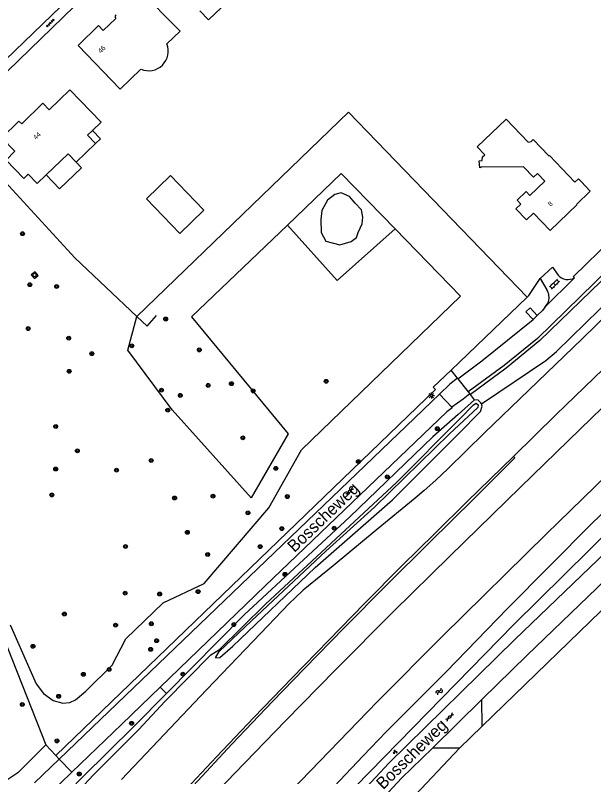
# Model space of a CAD drawing. Extents: x 137999 to 141000, y 397500 to 400501.
# Drawn here: x 138562.8 to 138683.2, y 399077.5 to 399235.9 of the extents above; entities that cross this region are included whole.
import ezdxf

# ---------------------------------------------------------------- set-up
doc = ezdxf.new("R2010")
doc.units = 0
for name, color, linetype in [('gg-afsc-draadraster', 7, 'Continuous'), ('gg-afsc-erfafscheiding', 7, 'Continuous'), ('gg-afsc-hekwerk', 7, 'Continuous'), ('gg-afsc-lijn draadraster', 7, 'Continuous'), ('gg-afsc-muur', 7, 'Continuous'), ('gg-anno-huisnummerreeks BGT', 7, 'Continuous'), ('gg-anno-openbare ruimte label', 7, 'Continuous'), ('gg-bbg-gedigitaliseerde bebouwing', 7, 'Continuous'), ('gg-bbg-gedigitaliseerde bijgebouw', 7, 'Continuous'), ('gg-bbg-hoofdgebouw', 7, 'Continuous'), ('gg-bbg-luifel en loopbrug', 7, 'Continuous'), ('gg-knt-BGT kruinlijn', 7, 'Continuous'), ('gg-knt-bronhoudergrens', 7, 'Continuous'), ('gg-knt-verharding', 7, 'Continuous'), ('gg-kntw-bovenkant insteek waterloop', 7, 'Continuous'), ('gg-kwrk-keermuur', 7, 'Continuous'), ('gt-grn-groengrens', 7, 'Continuous'), ('gt-grn-weggrens', 7, 'Continuous'), ('gt-symb-boom', 7, 'Continuous'), ('gt-symb-gesloten verharding', 7, 'Continuous'), ('gt-symb-groenvak', 7, 'Continuous'), ('gt-symb-klinker verharding', 7, 'Continuous'), ('gt-symb-lichtmast', 7, 'Continuous'), ('gt-symb-rioolschacht', 7, 'Continuous'), ('gt-symb-tegel verharding', 7, 'Continuous'), ('gt-symb-watersymbool', 7, 'Continuous'), ('gx-grn-maaiveld', 7, 'Continuous')]:
    doc.layers.add(name, color=color, linetype=linetype)

# ---------------------------------------------------------------- blocks, each defined once
blk = doc.blocks.new('gt0-KL1')
at = {"layer": 'gt-symb-klinker verharding'}
for p, q in [((-1.15, 0.3), (1.15, 0.3)), ((-1, -0.3), (-1, 0.3)), ((-0.5, 0.3), (-0.5, 0.45)), ((0, -0.3), (0, 0.3)), ((0.5, 0.3), (0.5, 0.45)), ((1, -0.3), (1, 0.3)), ((-1.15, -0.3), (1.15, -0.3)), ((-0.5, -0.45), (-0.5, -0.3)), ((0.5, -0.45), (0.5, -0.3))]:
    blk.add_line(p, q, dxfattribs=at)
blk = doc.blocks.new('gt0-LMAST')
at = {"layer": 'gt-symb-lichtmast'}
for p, q in [((-0.18, 0.17), (-0.45, 0.44)), ((0, 0.25), (0, 0.62)), ((0.17, 0.17), (0.44, 0.44)), ((-0.25, 0), (-0.63, 0)), ((-0.18, -0.18), (-0.45, -0.45)), ((0, -0.25), (0, -0.63)), ((0.44, -0.45), (0.17, -0.18)), ((0.25, 0), (0.62, 0))]:
    blk.add_line(p, q, dxfattribs=at)
blk.add_circle((0, 0), 0.25, dxfattribs=at)
blk = doc.blocks.new('gt0-BOOM')
at = {"layer": 'gt-symb-boom'}
for radius in [0.4, 0.2]:
    blk.add_circle((0, 0), radius, dxfattribs=at)
blk = doc.blocks.new('gt0-GESVH1')
at = {"layer": 'gt-symb-gesloten verharding'}
for p, q in [((-0.99, -0.26), (0.01, 0.24)), ((0.01, -0.26), (-0.99, 0.24)), ((0.01, 0.24), (1.01, -0.26)), ((1.01, 0.24), (0.01, -0.26))]:
    blk.add_line(p, q, dxfattribs=at)
blk = doc.blocks.new('gt0-RS')
at = {"layer": 'gt-symb-rioolschacht'}
blk.add_lwpolyline([(-0.5, -0.5), (0.5, -0.5), (0.5, 0.5), (-0.5, 0.5)], close=True, dxfattribs=at)
blk.add_circle((0, 0), 0.375, dxfattribs=at)
blk = doc.blocks.new('gt0-TEG1')
at = {"layer": 'gt-symb-tegel verharding'}
for p, q in [((-1.13, 0), (1.12, 0)), ((-0.9, -0.25), (-0.9, 0.25)), ((-0.45, -0.25), (-0.45, 0.25)), ((0, -0.25), (0, 0.25)), ((0.45, -0.25), (0.45, 0.25)), ((0.9, -0.25), (0.9, 0.25))]:
    blk.add_line(p, q, dxfattribs=at)
blk = doc.blocks.new('gt0-GRVAK')
at = {"layer": 'gt-symb-groenvak'}
for p, q in [((-0.11, 0.19), (-0.23, 0.24)), ((-0.18, 0.15), (0.09, 0.15)), ((-0.09, 0.21), (-0.16, 0.32)), ((-0.05, 0.21), (-0.05, 0.39)), ((0, 0.21), (0.06, 0.32)), ((0.02, 0.19), (0.13, 0.24)), ((0.26, -0.05), (0.2, 0.06)), ((0.31, -0.05), (0.31, 0.13)), ((0.35, -0.05), (0.41, 0.06)), ((-0.24, -0.23), (-0.36, -0.18)), ((-0.32, -0.26), (-0.05, -0.26)), ((-0.23, -0.21), (-0.29, -0.09)), ((-0.18, -0.2), (-0.18, -0.02)), ((-0.14, -0.21), (-0.07, -0.09)), ((-0.12, -0.23), (0, -0.18)), ((0.24, -0.07), (0.12, -0.02)), ((0.17, -0.11), (0.44, -0.11)), ((0.37, -0.07), (0.49, -0.02))]:
    blk.add_line(p, q, dxfattribs=at)
blk = doc.blocks.new('gt0-WA')
at = {"layer": 'gt-symb-watersymbool'}
for centre, start, end in [((-0.32, 0.02), 28.0725, 151.9275), ((0.43, 0.42), 208.0725, 331.9275), ((-0.32, -0.43), 28.0725, 151.9275), ((0.43, -0.03), 208.0725, 331.9275)]:
    blk.add_arc(centre, 0.425, start, end, dxfattribs=at)

msp = doc.modelspace()

# ---------------------------------------------------------------- linework, layer by layer
at = {"layer": 'gg-afsc-draadraster'}
for p, q in [((138653.48, 399162.09), (138669.32, 399177.31)), ((138649.77, 399158.53), (138653.48, 399162.09))]:
    msp.add_line(p, q, dxfattribs=at)
msp.add_lwpolyline([(138669.32, 399177.31), (138669.64, 399177.61), (138672, 399181.18)], dxfattribs=at)
at = {"layer": 'gg-afsc-erfafscheiding'}
for points in [[(138558.28, 399203.76), (138575.15, 399185.44), (138588.09, 399173.24)], [(138588.09, 399173.24), (138590.2, 399171.25), (138592.17, 399173.46)]]:
    msp.add_lwpolyline(points, dxfattribs=at)
at = {"layer": 'gg-afsc-hekwerk'}
for p, q in [((138542.31, 399151.33), (138569.15, 399084.11)), ((138569.15, 399084.11), (138565.97, 399080.94))]:
    msp.add_line(p, q, dxfattribs=at)
msp.add_lwpolyline([(138565.97, 399080.94), (138563.3, 399078.28), (138558.06, 399074.85), (138539.36, 399056.53), (138534.35, 399053.22), (138530.38, 399049.44)], dxfattribs=at)
at = {"layer": 'gg-afsc-lijn draadraster'}
msp.add_line((138653.48, 399162.09), (138669.32, 399177.31), dxfattribs=at)
msp.add_lwpolyline([(138669.32, 399177.31), (138669.64, 399177.61), (138672, 399181.18)], dxfattribs=at)
at = {"layer": 'gg-afsc-muur'}
for p, q in [((138678.92, 399181.56), (138701.82, 399203.87)), ((138678.9, 399181.54), (138678.92, 399181.56))]:
    msp.add_line(p, q, dxfattribs=at)
at = {"layer": 'gg-bbg-gedigitaliseerde bebouwing'}
for p, q in [((138590.23, 399239.63), (138595.29, 399234.44)), ((138588.94, 399224.73), (138584.59, 399220.53)), ((138574.12, 399220.45), (138580.67, 399213.73)), ((138578.83, 399211.95), (138580.67, 399213.73)), ((138575.43, 399205.37), (138579.49, 399209.27))]:
    msp.add_line(p, q, dxfattribs=at)
for points in [[(138606.6, 399242.05), (138608.37, 399240.22), (138602.96, 399235), (138601.19, 399236.83)], [(138594.32, 399229.97), (138597.06, 399232.61), (138595.29, 399234.44)], [(138579.49, 399209.27), (138577.83, 399210.99), (138578.83, 399211.95)], [(138569.23, 399202.72), (138573.77, 399207.09), (138575.43, 399205.37)], [(138564.55, 399201.96), (138565.47, 399202.85), (138567.35, 399200.91), (138569.23, 399202.72)]]:
    msp.add_lwpolyline(points, dxfattribs=at)
msp.add_arc((138590.55, 399228.46), 4.06, 246.7026, 21.8182, dxfattribs=at)
at = {"layer": 'gg-bbg-gedigitaliseerde bijgebouw'}
msp.add_lwpolyline([(138590.06, 399197.71), (138597.02, 399190.53), (138602.05, 399195.41), (138595.08, 399202.58), (138590.06, 399197.71)], dxfattribs=at)
at = {"layer": 'gg-bbg-hoofdgebouw'}
msp.add_line((138584.59, 399220.53), (138575.83, 399229.62), dxfattribs=at)
for points in [[(138583.7, 399235.29), (138581.05, 399232.77), (138580.09, 399233.78), (138575.83, 399229.62)], [(138574.12, 399220.45), (138569.82, 399216.24), (138568.5, 399217.62), (138564.12, 399213.35), (138563.55, 399213.93), (138559.97, 399210.45), (138562.67, 399207.66)], [(138666.96, 399195.65), (138667.98, 399196.63), (138667.21, 399197.43), (138669.11, 399199.25), (138669.88, 399198.45), (138672.99, 399201.42), (138671.45, 399203.03), (138670.62, 399202.24), (138668.55, 399204.41), (138659.65, 399204.34), (138659.66, 399204.23), (138659.44, 399204.21), (138659.29, 399205.62), (138659.94, 399205.69), (138660.02, 399206.46), (138660.47, 399206.89), (138658.89, 399208.53), (138664.94, 399214.33), (138669.51, 399209.56), (138670.12, 399209.65), (138670.56, 399210.07), (138673.83, 399206.66), (138673.92, 399206.75), (138679.22, 399201.22), (138679.97, 399201.93), (138680.51, 399201.36)], [(138564.55, 399201.96), (138560.86, 399205.8), (138562.67, 399207.66)], [(138666.96, 399195.65), (138669.15, 399193.37), (138670.59, 399194.79), (138674.07, 399191.12), (138679.67, 399196.48), (138679.57, 399196.58), (138682.43, 399199.36), (138680.51, 399201.36)]]:
    msp.add_lwpolyline(points, dxfattribs=at)
msp.add_arc((138584.01, 399235.65), 0.474, 132.2853, 229.3286, dxfattribs=at)
at = {"layer": 'gg-bbg-luifel en loopbrug'}
for points in [[(138579.49, 399209.27), (138580.49, 399210.25), (138578.83, 399211.95)], [(138569.23, 399202.72), (138571.99, 399199.85), (138576.54, 399204.22), (138575.43, 399205.37)]]:
    msp.add_lwpolyline(points, dxfattribs=at)
at = {"layer": 'gg-knt-BGT kruinlijn'}
for p, q in [((138659.03, 399154.3), (138653.13, 399148.84)), ((138655.39, 399152.05), (138658.14, 399154.89)), ((138658.14, 399154.89), (138658.67, 399155.19)), ((138658.67, 399155.19), (138659.12, 399154.9)), ((138659.12, 399154.9), (138659.03, 399154.3)), ((138642.14, 399138.68), (138655.39, 399152.05)), ((138653.13, 399148.84), (138637.55, 399133.57)), ((138614.86, 399113.4), (138642.14, 399138.68)), ((138637.55, 399133.57), (138627.44, 399124.44)), ((138627.44, 399124.44), (138611.96, 399109.92)), ((138605.31, 399103.93), (138614.86, 399113.4)), ((138611.96, 399109.92), (138605.23, 399103.51)), ((138603.46, 399102.83), (138605.31, 399103.93)), ((138604.47, 399102.19), (138605.23, 399103.51)), ((138593.94, 399093.2), (138603.46, 399102.83)), ((138588.4, 399087.23), (138593.94, 399093.2)), ((138579.08, 399077.9), (138588.4, 399087.23)), ((138572.03, 399070.45), (138579.08, 399077.9))]:
    msp.add_line(p, q, dxfattribs=at)
at = {"layer": 'gg-knt-bronhoudergrens'}
for p, q in [((138654.79, 399160.42), (138653.48, 399162.09)), ((138650.24, 399158.03), (138649.77, 399158.53))]:
    msp.add_line(p, q, dxfattribs=at)
at = {"layer": 'gg-knt-verharding'}
for p, q in [((138560.77, 399226.68), (138577.84, 399243.22)), ((138654.79, 399160.42), (138653.24, 399159.19)), ((138653.24, 399159.19), (138651.09, 399157.12)), ((138651.09, 399157.12), (138571.91, 399081.14)), ((138651.09, 399157.12), (138653.61, 399154.38)), ((138653.73, 399154.25), (138652.57, 399153.41)), ((138653.61, 399154.38), (138653.73, 399154.25)), ((138614.79, 399117.23), (138652.57, 399153.41)), ((138592.93, 399096.13), (138614.79, 399117.23)), ((138571.91, 399081.14), (138566.76, 399076.2)), ((138563.14, 399067.46), (138574.54, 399078.41))]:
    msp.add_line(p, q, dxfattribs=at)
for points in [[(138673.34, 399332.19), (138639.6, 399299.52), (138632.54, 399299.67), (138589.36, 399258.02), (138588.89, 399251.3), (138549.57, 399213.15)], [(138571.8, 399000), (138584.07, 399016.51), (138612.13, 399049.83), (138640.56, 399080.38), (138666.74, 399106.01), (138694.44, 399132.57), (138762.01, 399197.52), (138807.68, 399242.38), (138884.6, 399318.08), (138886.05, 399319.54)], [(138672, 399181.18), (138674.55, 399183.49), (138675.73, 399181.86)], [(138657.36, 399157.16), (138655.96, 399156.07), (138653.61, 399154.38)], [(138574.54, 399078.41), (138584.96, 399088.43), (138592.93, 399096.13)]]:
    msp.add_lwpolyline(points, dxfattribs=at)
at = {"layer": 'gg-kntw-bovenkant insteek waterloop'}
msp.add_lwpolyline([(138569.06, 399000), (138599.49, 399037.92), (138630.55, 399072.31), (138666.53, 399109.13), (138692.73, 399135.04), (138766.57, 399206.06), (138805.76, 399244.25), (138841.1, 399278.43), (138881.4, 399317.3), (138882.07, 399318.34)], dxfattribs=at)
at = {"layer": 'gg-kwrk-keermuur'}
msp.add_line((138678.92, 399181.56), (138701.82, 399203.87), dxfattribs=at)
at = {"layer": 'gt-grn-groengrens'}
for p, q in [((138641.82, 399191.5), (138655.44, 399177.49)), ((138571.2, 399081.91), (138650.24, 399158.03)), ((138594.22, 399094.8), (138592.93, 399096.13)), ((138571.2, 399081.91), (138569.15, 399084.11)), ((138571.91, 399081.14), (138571.2, 399081.91))]:
    msp.add_line(p, q, dxfattribs=at)
for points in [[(138669.32, 399177.31), (138632.14, 399215.77), (138588.09, 399173.24)], [(138641.82, 399191.5), (138630.63, 399203.02), (138619.4, 399192.26)], [(138633.77, 399189.67), (138634.15, 399190.71), (138634.95, 399192.54), (138635.14, 399193.96), (138634.8, 399195.45), (138633.5, 399196.83), (138632.35, 399198.21), (138630.59, 399199.01), (138629.29, 399198.63), (138627.76, 399197.44), (138626.54, 399195.3), (138626.38, 399193.46), (138626.42, 399190.74), (138627.38, 399188.95), (138630.32, 399188.18), (138632.69, 399188.87), (138633.77, 399189.67)], [(138619.4, 399192.26), (138599.47, 399173.16), (138619.56, 399148.86), (138611.85, 399135.55), (138595.46, 399153.8), (138586.22, 399166.27), (138588.09, 399173.24)], [(138641.82, 399191.5), (138629.78, 399180.77), (138619.4, 399192.26)], [(138561.7, 399109.1), (138565.8, 399099.77), (138567.14, 399096.82), (138568.62, 399094.81), (138570.63, 399093.33), (138572.64, 399092.8), (138574.11, 399092.93), (138575.32, 399093.47), (138577.46, 399095.3), (138582.95, 399100.66), (138585.77, 399106.16), (138593.54, 399113.67), (138602.12, 399117.69), (138615.51, 399133.45), (138622.34, 399145.51), (138655.44, 399177.49)]]:
    msp.add_lwpolyline(points, dxfattribs=at)
at = {"layer": 'gt-grn-weggrens'}
msp.add_line((138571.91, 399081.14), (138574.54, 399078.41), dxfattribs=at)
at = {"layer": 'gx-grn-maaiveld'}
for p, q in [((138672, 399181.18), (138673.43, 399178.77)), ((138679.16, 399181.31), (138678.92, 399181.56)), ((138679.16, 399181.31), (138679.15, 399181.31)), ((138671.42, 399173.46), (138670.54, 399172.64)), ((138654.88, 399160.31), (138654.79, 399160.42)), ((138654.88, 399160.31), (138657.05, 399157.55)), ((138735.88, 399161.6), (138659.92, 399088)), ((138657.05, 399157.55), (138657.36, 399157.16)), ((138657.36, 399157.16), (138657.49, 399157)), ((138658.37, 399155.88), (138657.49, 399157)), ((138659.87, 399093.52), (138649.62, 399083.44)), ((138659.92, 399088), (138659.87, 399093.52)), ((138659.92, 399088), (138655.21, 399083.4)), ((138655.21, 399083.4), (138618.61, 399044.8)), ((138655.21, 399083.4), (138649.62, 399083.44))]:
    msp.add_line(p, q, dxfattribs=at)
for points in [[(138763.86, 399258.76), (138757.1, 399252.18), (138744.99, 399240.36), (138733.25, 399228.91), (138722.42, 399218.36), (138709.95, 399206.19), (138698.33, 399194.85), (138686.32, 399183.14), (138671.49, 399168.71), (138664.52, 399163.06), (138657.05, 399157.55)], [(138764.45, 399258.41), (138757.56, 399251.7), (138745.46, 399239.9), (138733.73, 399228.4), (138710.44, 399205.69), (138698.76, 399194.36), (138686.8, 399182.65), (138671.97, 399168.24), (138664.93, 399162.51), (138657.49, 399157)], [(138659.77, 399155.09), (138673.16, 399164.09), (138675.41, 399166), (138690.35, 399180.57), (138702.07, 399192.01), (138726.21, 399215.44), (138747.84, 399236.61), (138761.84, 399250.12), (138768.31, 399256.42)], [(138666.44, 399144.15), (138675.36, 399152.88), (138685.11, 399162.29), (138697.02, 399173.84), (138704.59, 399181.28), (138714.01, 399190.41), (138726.38, 399202.33), (138736.1, 399211.81), (138747.46, 399222.75), (138760.29, 399235.26), (138775.8, 399250.27), (138777.29, 399251.74)], [(138782.72, 399248.98), (138780.45, 399246.78), (138754.03, 399221.18), (138729.59, 399197.44), (138715.3, 399183.49), (138703.21, 399172.02), (138691.93, 399161.06), (138680.32, 399149.78), (138667.89, 399137.77), (138653.22, 399123.39), (138641.49, 399111.83), (138629.42, 399099.73), (138619, 399089.09), (138608.45, 399078.21), (138595.11, 399064.19), (138584.24, 399052.51), (138573.94, 399041.33), (138564.83, 399031.26), (138555.63, 399021.02), (138546.98, 399011.39), (138536.29, 398999.15), (138526.38, 398987.5), (138517.55, 398976.85), (138515.33, 398974.12)], [(138563.93, 398999.16), (138566.36, 399001.99), (138568.83, 399004.91), (138590.2, 399031.73), (138597.25, 399040.05), (138601.66, 399045.12), (138612.41, 399057.05), (138626.74, 399072.88), (138635.18, 399081.84), (138639.93, 399086.79), (138652.44, 399099.34), (138665.21, 399112.5), (138682.74, 399130.2), (138695.72, 399142.58), (138708.72, 399155.24), (138724.56, 399170.64), (138740.53, 399185.68), (138760.84, 399205.22)], [(138679.15, 399181.31), (138678.93, 399181.09), (138673.08, 399175.29)], [(138673.55, 399175.96), (138673.55, 399175.97), (138673.6, 399176.07), (138673.72, 399176.36), (138673.8, 399176.66), (138673.85, 399176.97), (138673.86, 399177.29), (138673.84, 399177.6), (138673.79, 399177.91), (138673.7, 399178.21), (138673.58, 399178.5), (138673.43, 399178.77)], [(138689.53, 399177.18), (138680.74, 399168.62), (138669.68, 399157.95), (138660.41, 399149.01), (138652.8, 399141.54), (138650.28, 399139.18), (138647.84, 399137.01), (138645.98, 399135.42), (138637.9, 399128.8), (138628.93, 399121.4), (138622.69, 399116.27), (138621.03, 399114.7), (138619.84, 399113.57), (138612.29, 399105.71), (138602.55, 399095.54), (138593.78, 399086.27), (138584.85, 399076.88)], [(138673.55, 399175.96), (138672.51, 399174.52), (138671.42, 399173.46)], [(138673.08, 399175.29), (138673.28, 399175.53), (138673.46, 399175.79), (138673.55, 399175.96)], [(138671.42, 399173.46), (138669.91, 399175.06), (138669.04, 399174.24), (138670.54, 399172.64)], [(138654.88, 399160.31), (138659.86, 399164), (138670.54, 399172.64)], [(138730.8, 399161.76), (138707.48, 399139.48), (138669.29, 399102.77), (138659.87, 399093.52)], [(138703.72, 399157.61), (138673.36, 399128.03), (138651.73, 399106.8), (138638.1, 399093.03), (138620.18, 399074.56), (138610.88, 399064.72), (138600.97, 399053.71), (138594.4, 399046.24), (138587.84, 399038.5), (138579.97, 399029.04), (138567.33, 399013.21), (138559.01, 399002.34), (138548.19, 398988.32), (138539.9, 398977.4), (138531.5, 398966.26), (138531.08, 398965.68)], [(138658.37, 399155.88), (138654.98, 399152.89), (138649.68, 399148.24), (138632.35, 399131.46), (138610.44, 399111.18), (138594.22, 399094.8)], [(138659.77, 399155.09), (138659.69, 399155.3), (138659.13, 399155.81), (138658.37, 399155.88)], [(138604.47, 399102.19), (138605.38, 399102.28), (138608.05, 399104.64), (138625.18, 399121.03), (138641.3, 399135.12), (138655.04, 399148.85), (138659.57, 399153.45), (138659.95, 399154.6), (138659.77, 399155.09)], [(138511.96, 398975.93), (138515.83, 398980.7), (138525.39, 398992.27), (138536.52, 399005.52), (138551.89, 399023.52), (138558.42, 399030.91), (138566.13, 399039.6), (138574.37, 399048.73), (138581.76, 399056.83), (138589.86, 399065.69), (138597.36, 399073.85), (138604.67, 399081.63), (138612.45, 399089.8), (138620.3, 399098), (138628.01, 399105.89), (138635.47, 399113.55), (138643.22, 399121.37), (138650.06, 399128.09), (138656.84, 399134.77), (138666.44, 399144.15)], [(138512.45, 398975.67), (138513.49, 398976.96), (138522.56, 398987.83), (138534.29, 399001.78), (138543.64, 399012.81), (138552.38, 399023.19), (138556.22, 399027.66), (138564.79, 399037.25), (138575.85, 399049.57), (138583.75, 399058.11), (138592.12, 399067.28), (138599.86, 399075.68), (138607.86, 399084.24), (138616.3, 399093.11), (138623, 399100), (138631.24, 399108.46), (138640.11, 399117.39), (138648.97, 399126.19), (138658.18, 399135.3), (138666.77, 399143.83), (138666.44, 399144.15)], [(138563.06, 399061.32), (138567.07, 399066.81), (138571.24, 399071.68), (138576.83, 399077.45), (138587.43, 399087.94), (138594.22, 399094.8)], [(138596.49, 399025.09), (138615.03, 399046.87), (138643.18, 399077.18), (138649.62, 399083.44)]]:
    msp.add_lwpolyline(points, dxfattribs=at)
msp.add_arc((138677.79, 399183.74), 2.79, 222.4307, 299.394, dxfattribs=at)

# ---------------------------------------------------------------- block references
at = {"layer": 'gt-symb-boom'}
for p in [(138564.29, 399190.48), (138565.81, 399179.87), (138571.38, 399179.5), (138594.08, 399172.73), (138565.47, 399170.74), (138573.9, 399168.75), (138587.04, 399167.14), (138601.07, 399166.3), (138578.71, 399165.52), (138573.98, 399161.85), (138627.47, 399159.77), (138602.93, 399158.91), (138607.76, 399159.28), (138593.2, 399157.92), (138597.12, 399156.83), (138612.29, 399157.77), (138594.51, 399153.77), (138571.19, 399150.37), (138650.61, 399149.9), (138610.13, 399148.01), (138575.7, 399145.3), (138591.05, 399143.29), (138634.18, 399143.05), (138571.18, 399141.51), (138583.83, 399141.27), (138617, 399141.65), (138640.19, 399139.89), (138570.38, 399136.12), (138595.93, 399135.48), (138603.92, 399135.87), (138619.39, 399135.78), (138611.2, 399132.39), (138598.59, 399128.34), (138618.26, 399129.11), (138629.14, 399129.2), (138585.71, 399125.4), (138613.75, 399125.37), (138602.82, 399123.73), (138618.91, 399119.6), (138585.64, 399115.67), (138592.83, 399115.49), (138600.82, 399116), (138573, 399111.33), (138583.66, 399109.01), (138591.09, 399109.31), (138608.27, 399109.14), (138566.45, 399104.62), (138592.19, 399105.78), (138590.95, 399103.98), (138582.31, 399099.79), (138576.95, 399098.79), (138597.64, 399098.82), (138571.81, 399094.22), (138564.23, 399092.51), (138586.98, 399088.6), (138571.45, 399084.93), (138576.09, 399078.05)]:
    msp.add_blockref('gt0-BOOM', p, dxfattribs=at)
at = {"layer": 'gt-symb-gesloten verharding'}
for p, rotation in [((138632.33, 399136.85), 45.972395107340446), ((138653.17, 399089.92), 44.51376743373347)]:
    msp.add_blockref('gt0-GESVH1', p, dxfattribs=dict(at, rotation=rotation))
at = {"layer": 'gt-symb-groenvak'}
msp.add_blockref('gt0-GRVAK', (138641.8, 399082.65), dxfattribs=at)
at = {"layer": 'gt-symb-klinker verharding', "rotation": -135.89137585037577}
msp.add_blockref('gt0-KL1', (138675, 399179.99), dxfattribs=at)
at = {"layer": 'gt-symb-lichtmast'}
msp.add_blockref('gt0-LMAST', (138649.38, 399156.8), dxfattribs=at)
at = {"layer": 'gt-symb-rioolschacht', "rotation": -141.17017509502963}
msp.add_blockref('gt0-RS', (138566.82, 399181.88), dxfattribs=at)
at = {"layer": 'gt-symb-tegel verharding', "rotation": 45.97239510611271}
msp.add_blockref('gt0-TEG1', (138570.09, 399234.33), dxfattribs=at)
at = {"layer": 'gt-symb-watersymbool', "rotation": 44.51376743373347}
msp.add_blockref('gt0-WA', (138650.96, 399095.17), dxfattribs=at)

# ---------------------------------------------------------------- texts
at = {"layer": 'gg-anno-huisnummerreeks BGT'}
for s, rotation, p in [('46', 44.4, (138580.56, 399227.95)), ('44', 44.3, (138567.09, 399209.96)), ('8', 43.8, (138674.18, 399196.07))]:
    msp.add_text(s, height=1, rotation=rotation, dxfattribs=at).set_placement(p)
at = {"layer": 'gg-anno-openbare ruimte label'}
for s, rotation, p in [('Tobias Asserlaan', 44.2, (138552.65, 399230.5)), ('Bosscheweg', 43.9, (138620.88, 399124.02)), ('Bosscheweg', 44.4, (138639.34, 399074.68))]:
    msp.add_text(s, height=2.5, rotation=rotation, dxfattribs=at).set_placement(p)

doc.saveas('drawing.dxf')
